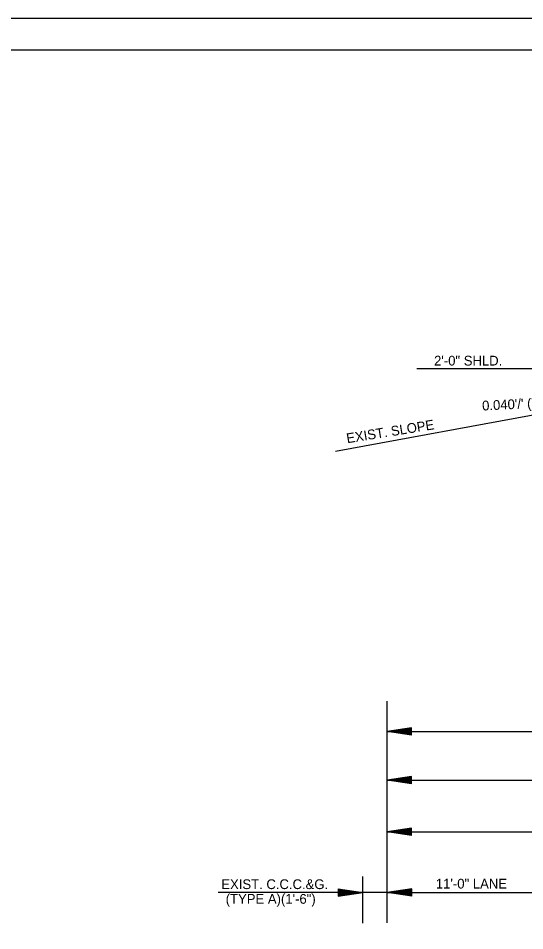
# Model space of a CAD drawing. Extents: x 2263886 to 2266026, y -3122850 to -3121850.
# Drawn here: x 2265715.1 to 2265746.1, y -3122393.1 to -3122337.2 of the extents above; entities that cross this region are included whole.
import ezdxf

# ---------------------------------------------------------------- set-up
doc = ezdxf.new("R2010")
doc.units = 0
for name, color, linetype in [('_CIVIL_CONSTRUCTION', 7, 'Continuous'), ('R_Border Prem', 7, 'Continuous'), ('R_Draft', 7, 'Continuous')]:
    doc.layers.add(name, color=color, linetype=linetype)

msp = doc.modelspace()

# ---------------------------------------------------------------- linework, layer by layer
at = {"layer": '_CIVIL_CONSTRUCTION'}
msp.add_line((2265692.365, -3122337.151), (2265859.032, -3122337.151), dxfattribs=at)
for points in [[(2265692.362, -3122337.151), (2265859.032, -3122337.151), (2265859.032, -3122443.82), (2265692.362, -3122443.82)], [(2265815.526, -3122339.098), (2265815.526, -3122344.038), (2265833.392, -3122344.038), (2265833.392, -3122345.498), (2265844.991, -3122345.498), (2265844.991, -3122357.664), (2265856.656, -3122357.664), (2265856.656, -3122441.828), (2265698.566, -3122441.828), (2265698.566, -3122339.098)]]:
    msp.add_lwpolyline(points, close=True, dxfattribs=at)
at = {"layer": 'R_Border Prem'}
for p, q in [((2265749.787, -3122358.661), (2265739.51, -3122358.661)), ((2265747.756, -3122361.299), (2265734.532, -3122363.728)), ((2265737.699, -3122390.794), (2265737.699, -3122379.051)), ((2265739.199, -3122380.692), (2265737.699, -3122380.917)), ((2265739.199, -3122380.73), (2265737.95, -3122380.917)), ((2265739.199, -3122380.768), (2265738.208, -3122380.917)), ((2265739.199, -3122381.142), (2265739.199, -3122380.692)), ((2265739.199, -3122381.142), (2265737.699, -3122380.917)), ((2265737.699, -3122380.918), (2265804.699, -3122380.918)), ((2265739.199, -3122381.105), (2265737.95, -3122380.917)), ((2265739.199, -3122381.066), (2265738.208, -3122380.917)), ((2265739.199, -3122380.805), (2265738.457, -3122380.917)), ((2265739.199, -3122381.029), (2265738.457, -3122380.917)), ((2265739.199, -3122380.844), (2265738.712, -3122380.917)), ((2265739.199, -3122380.99), (2265738.712, -3122380.917)), ((2265739.199, -3122380.882), (2265738.962, -3122380.917)), ((2265739.199, -3122380.952), (2265738.962, -3122380.917)), ((2265739.199, -3122383.681), (2265737.699, -3122383.906)), ((2265739.199, -3122384.131), (2265737.699, -3122383.906)), ((2265737.699, -3122383.907), (2265804.699, -3122383.907)), ((2265739.199, -3122383.719), (2265737.95, -3122383.906)), ((2265739.199, -3122384.094), (2265737.95, -3122383.906)), ((2265739.199, -3122383.757), (2265738.208, -3122383.906)), ((2265739.199, -3122384.055), (2265738.208, -3122383.906)), ((2265739.199, -3122383.794), (2265738.457, -3122383.906)), ((2265739.199, -3122384.018), (2265738.457, -3122383.906)), ((2265739.199, -3122383.833), (2265738.712, -3122383.906)), ((2265739.199, -3122383.979), (2265738.712, -3122383.906)), ((2265739.199, -3122383.871), (2265738.962, -3122383.906)), ((2265739.199, -3122383.941), (2265738.962, -3122383.906)), ((2265739.199, -3122384.131), (2265739.199, -3122383.681)), ((2265739.199, -3122386.844), (2265737.699, -3122387.069)), ((2265739.199, -3122386.881), (2265737.95, -3122387.069)), ((2265739.199, -3122386.919), (2265738.208, -3122387.069)), ((2265739.199, -3122387.294), (2265739.199, -3122386.844)), ((2265737.699, -3122387.068), (2265804.699, -3122387.068)), ((2265739.199, -3122387.294), (2265737.699, -3122387.069)), ((2265739.199, -3122387.256), (2265737.95, -3122387.069)), ((2265739.199, -3122387.218), (2265738.208, -3122387.069)), ((2265739.199, -3122386.957), (2265738.457, -3122387.069)), ((2265739.199, -3122387.18), (2265738.457, -3122387.069)), ((2265739.199, -3122386.995), (2265738.712, -3122387.069)), ((2265739.199, -3122387.141), (2265738.712, -3122387.069)), ((2265739.199, -3122387.033), (2265738.962, -3122387.069)), ((2265739.199, -3122387.104), (2265738.962, -3122387.069)), ((2265736.199, -3122392.677), (2265736.199, -3122389.805)), ((2265737.699, -3122392.66), (2265737.699, -3122389.805)), ((2265737.699, -3122390.794), (2265727.326, -3122390.794)), ((2265734.698, -3122390.57), (2265736.198, -3122390.795)), ((2265734.698, -3122390.57), (2265734.698, -3122391.02)), ((2265734.698, -3122390.607), (2265735.948, -3122390.795)), ((2265734.698, -3122390.646), (2265735.69, -3122390.795)), ((2265734.698, -3122390.683), (2265735.44, -3122390.795)), ((2265734.698, -3122390.722), (2265735.186, -3122390.795)), ((2265734.698, -3122390.76), (2265734.935, -3122390.795)), ((2265734.698, -3122391.02), (2265736.198, -3122390.795)), ((2265734.698, -3122390.868), (2265735.186, -3122390.795)), ((2265734.698, -3122390.944), (2265735.69, -3122390.795)), ((2265734.698, -3122390.982), (2265735.948, -3122390.795)), ((2265734.698, -3122390.907), (2265735.44, -3122390.795)), ((2265734.698, -3122390.83), (2265734.935, -3122390.795)), ((2265737.699, -3122390.794), (2265748.699, -3122390.794)), ((2265739.206, -3122390.569), (2265737.706, -3122390.794)), ((2265739.206, -3122391.019), (2265737.706, -3122390.794)), ((2265739.206, -3122390.607), (2265737.957, -3122390.794)), ((2265739.206, -3122390.982), (2265737.957, -3122390.794)), ((2265739.206, -3122390.645), (2265738.215, -3122390.794)), ((2265739.206, -3122390.944), (2265738.215, -3122390.794)), ((2265739.206, -3122390.683), (2265738.465, -3122390.794)), ((2265739.206, -3122390.906), (2265738.465, -3122390.794)), ((2265739.206, -3122390.721), (2265738.719, -3122390.794)), ((2265739.206, -3122390.867), (2265738.719, -3122390.794)), ((2265739.206, -3122390.759), (2265738.969, -3122390.794)), ((2265739.206, -3122390.83), (2265738.969, -3122390.794)), ((2265739.206, -3122391.019), (2265739.206, -3122390.569))]:
    msp.add_line(p, q, dxfattribs=at)
at = {"layer": 'R_Draft'}
msp.add_line((2265698.566, -3122339.098), (2265856.656, -3122339.098), dxfattribs=at)

# ---------------------------------------------------------------- texts
at = {"layer": 'R_Border Prem'}
for s, p in [('2\'-0" SHLD.', (2265740.575, -3122358.462)), ('EXIST. C.C.C.&G.', (2265727.528, -3122390.588)), ('11\'-0" LANE', (2265740.685, -3122390.555)), ('(TYPE A)(1\'-6")', (2265727.797, -3122391.488))]:
    msp.add_text(s, height=0.6, dxfattribs=at).set_placement(p)
for s, rotation, p in [("0.040'/' (TYP.)", 2.8401, (2265743.537, -3122361.225)), ('EXIST. SLOPE', 9.1534, (2265735.249, -3122363.233))]:
    msp.add_text(s, height=0.6, rotation=rotation, dxfattribs=at).set_placement(p)

doc.saveas('drawing.dxf')
